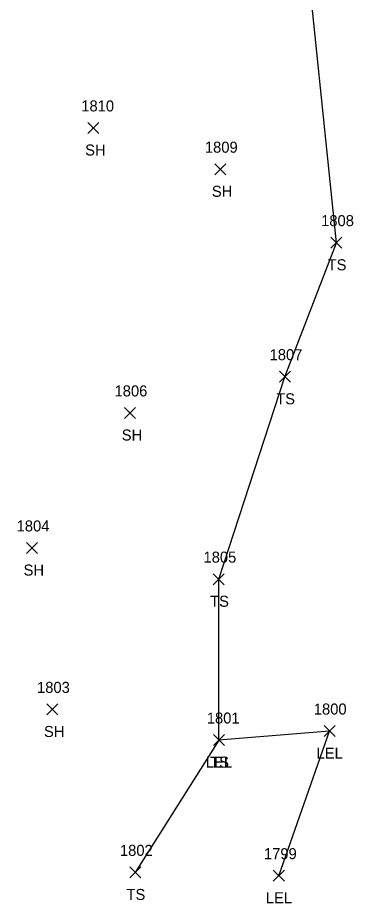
# Model space of a CAD drawing. Extents: x 1885914 to 1887218, y 756253 to 760620.
# Drawn here: x 1886343.7 to 1886404.5, y 759315.3 to 759475.9 of the extents above; entities that cross this region are included whole.
import ezdxf

# ---------------------------------------------------------------- set-up
doc = ezdxf.new("R2010")
doc.units = 0
for name, color, linetype in [('L_A', 7, 'Continuous'), ('L_I', 7, 'Continuous'), ('L_TIC', 7, 'Continuous'), ('LARO', 7, 'Continuous'), ('LELB', 7, 'Continuous')]:
    doc.layers.add(name, color=color, linetype=linetype)

msp = doc.modelspace()

# ---------------------------------------------------------------- linework, layer by layer
at = {"layer": 'L_TIC'}
for points in [[(1886356.43, 759454.89), (1886358.43, 759456.89)], [(1886358.43, 759454.89), (1886356.43, 759456.89)], [(1886379.41, 759447.4), (1886381.41, 759449.4)], [(1886381.41, 759447.4), (1886379.41, 759449.4)], [(1886400.48, 759434.08), (1886402.48, 759436.08)], [(1886402.48, 759434.08), (1886400.48, 759436.08)], [(1886391.15, 759409.77), (1886393.15, 759411.77)], [(1886393.15, 759409.77), (1886391.15, 759411.77)], [(1886363.07, 759403.2), (1886365.07, 759405.2)], [(1886365.07, 759403.2), (1886363.07, 759405.2)], [(1886345.27, 759378.71), (1886347.27, 759380.71)], [(1886347.27, 759378.71), (1886345.27, 759380.71)], [(1886379.16, 759373.05), (1886381.16, 759375.05)], [(1886381.16, 759373.05), (1886379.16, 759375.05)], [(1886348.97, 759349.43), (1886350.97, 759351.43)], [(1886350.97, 759349.43), (1886348.97, 759351.43)], [(1886399.24, 759345.5), (1886401.24, 759347.5)], [(1886401.24, 759345.5), (1886399.24, 759347.5)], [(1886379.18, 759343.87), (1886381.18, 759345.87)], [(1886381.18, 759343.87), (1886379.18, 759345.87)], [(1886379.18, 759343.87), (1886381.18, 759345.87)], [(1886381.18, 759343.87), (1886379.18, 759345.87)], [(1886379.18, 759343.87), (1886381.18, 759345.87)], [(1886381.18, 759343.87), (1886379.18, 759345.87)], [(1886364.01, 759319.87), (1886366.01, 759321.87)], [(1886366.01, 759319.87), (1886364.01, 759321.87)], [(1886390.04, 759319.27), (1886392.04, 759321.27)], [(1886392.04, 759319.27), (1886390.04, 759321.27)]]:
    msp.add_lwpolyline(points, dxfattribs=at)
at = {"layer": 'LARO'}
msp.add_lwpolyline([(1886391.04, 759320.27), (1886400.24, 759346.5), (1886380.18, 759344.87)], dxfattribs=at)
at = {"layer": 'LELB'}
for points in [[(1886380.18, 759344.87), (1886380.16, 759374.05), (1886392.15, 759410.77), (1886401.48, 759435.08), (1886395.25, 759495.48), (1886394.75, 759516.66), (1886388.53, 759529.6), (1886353.44, 759519.29)], [(1886380.18, 759344.87), (1886365.01, 759320.87)]]:
    msp.add_lwpolyline(points, dxfattribs=at)

# ---------------------------------------------------------------- texts
at = {"layer": 'L_A'}
for s, p in [('SH', (1886355.92, 759450.89)), ('SH', (1886378.9, 759443.4)), ('TS', (1886399.89, 759430.08)), ('TS', (1886390.56, 759405.77)), ('SH', (1886362.56, 759399.2)), ('SH', (1886344.76, 759374.71)), ('TS', (1886378.57, 759369.05)), ('SH', (1886348.46, 759345.43)), ('LEL', (1886397.88, 759341.5)), ('LEL', (1886377.82, 759339.87)), ('TS', (1886378.59, 759339.87)), ('TS', (1886378.59, 759339.87)), ('TS', (1886363.42, 759315.87)), ('LEL', (1886388.68, 759315.27))]:
    msp.add_text(s, height=2, dxfattribs=at).set_placement(p)
at = {"layer": 'L_I'}
for s, p in [('1810', (1886355.22, 759458.89)), ('1809', (1886377.63, 759451.4)), ('1808', (1886398.71, 759438.08)), ('1807', (1886389.37, 759413.77)), ('1806', (1886361.25, 759407.2)), ('1804', (1886343.5, 759382.71)), ('1805', (1886377.38, 759377.05)), ('1803', (1886347.2, 759353.43)), ('1800', (1886397.38, 759349.5)), ('1801', (1886377.98, 759347.87)), ('1801', (1886377.98, 759347.87)), ('1801', (1886377.98, 759347.87)), ('1802', (1886362.23, 759323.87)), ('1799', (1886388.34, 759323.27))]:
    msp.add_text(s, height=2, dxfattribs=at).set_placement(p)

doc.saveas('drawing.dxf')
